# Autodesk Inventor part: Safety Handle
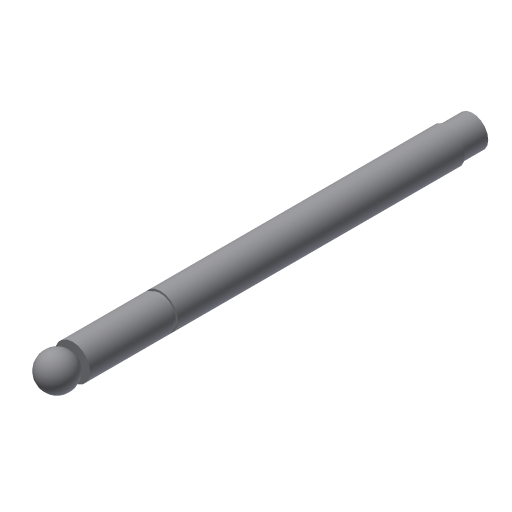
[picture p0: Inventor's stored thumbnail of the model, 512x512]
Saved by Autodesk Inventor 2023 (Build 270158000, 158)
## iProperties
Created: 2002-02
Part Number: Safety Handle
Document SubType Name: Modeling
Designer: ***
Density: 1 g/cm^3
Material: Generic
Mass: 54.3914 g
Surface Area: 130.219 cm^2
Volume: 54.3914 cm^3
Appearance: Default
Control State: 0
Master: False
Checked Out: False
Shininess: 77.0
Length Units: 11269
Angle Units: 11279
Time Units: 11290
Mass Units: 11283
Length Display Precision: 3
Angle Display Precision: 2
Density: 0.0
Volumn: 0.0
Area: 0.0
PropertySet Name: Model Information
Author: ***
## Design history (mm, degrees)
sketch "Sketch1"
  geometry: L1 (0, 205)-(8, 205); L2 (8, 205)-(8, 192); L3 (8, 192)-(9, 192); L4 (9, 192)-(9, 45); L5 (9, 45)-(8, 45); L6 (8, 45)-(8, 43); L7 (8, 43)-(9, 43); L8 (9, 43)-(9, 0); L9 (9, 0)-(0, 0); L10 (0, 0)-(0, 205)
  constraints: 20 end point, 7 parallel, 1 collinear, 1 horizontal, 1 perpendicular
  dimensions: "d0" = 13 distance of L1.end L2.end; "d1" = 2 distance of L4.end L7.end; "d2" = 43 distance of L7.end L8.end; "d3" = 205 distance of L9.end L1.start; "d4" = 16 diameter of L2 L10; "d5" = 18 diameter of L4 L10; "d6" = 16 diameter of L6.end L10
revolve "Revolution1" sketch "Sketch1" stored, may be unused: angle "d7" = 90 deg
sketch "Sketch2"
  geometry: L1 (0, 1)-(0, -17); L2 (-9, 0)-(9, 0) reference; A1 r 9 centre (0, -8) between (0, -17) and (0, 1)
  constraints: 2 end point, 2 point on circle, 1 centre point, 1 midpoint, 1 vertical
  dimensions: "d8" = 9 radius of A1; "d9" = 1 distance from line of L2 L1.start
revolve "Revolution2" sketch "Sketch2" stored, may be unused: angle "d10" = 90 deg
body "Solid1"
